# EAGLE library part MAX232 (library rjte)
RS232 TRANSEIVER
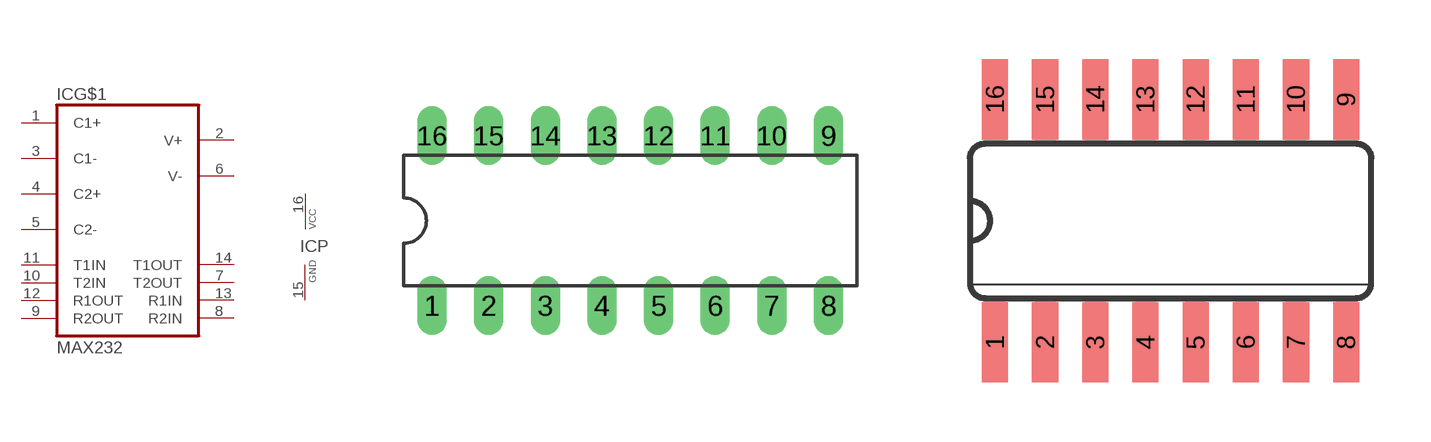
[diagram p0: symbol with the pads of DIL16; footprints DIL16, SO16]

Designator prefix IC; gates G$1=MAX232 P=VCC-GND

## MAX232DIP16  [DIL16]
1  G$1:C1+
2  G$1:V+
3  G$1:C1-
4  G$1:C2+
5  G$1:C2-
6  G$1:V-
7  G$1:T2OUT  out
8  G$1:R2IN  in
9  G$1:R2OUT  out
10  G$1:T2IN  in
11  G$1:T1IN  in
12  G$1:R1OUT  out
13  G$1:R1IN  in
14  G$1:T1OUT  out
15  P:GND  pwr
16  P:VCC  pwr

## MAX232SO16  [SO16]
Pads as for DIL16

## Footprint DIL16 (pad centres in mm)
Dual In Line Package
drill 0.813 long: 1 -8.89,-3.81; 2 -6.35,-3.81; 3 -3.81,-3.81; 4 -1.27,-3.81; 5 1.27,-3.81; 6 3.81,-3.81; 7 6.35,-3.81; 8 8.89,-3.81; 9 8.89,3.81; 10 6.35,3.81; 11 3.81,3.81; 12 1.27,3.81; 13 -1.27,3.81; 14 -3.81,3.81; 15 -6.35,3.81; 16 -8.89,3.81

## Footprint SO16 (pad centres in mm)
Small Outline Package .150 SIOC Source: http://www.maxim-ic.com/package_drawings/21-0041B.pdf
smd 0.66 x 2.032: 1 -4.445,-3.073; 2 -3.175,-3.073; 3 -1.905,-3.073; 4 -0.635,-3.073; 5 0.635,-3.073; 6 1.905,-3.073; 7 3.175,-3.073; 8 4.445,-3.073; 9 4.445,3.073; 10 3.175,3.073; 11 1.905,3.073; 12 0.635,3.073; 13 -0.635,3.073; 14 -1.905,3.073; 15 -3.175,3.073; 16 -4.445,3.073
